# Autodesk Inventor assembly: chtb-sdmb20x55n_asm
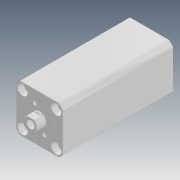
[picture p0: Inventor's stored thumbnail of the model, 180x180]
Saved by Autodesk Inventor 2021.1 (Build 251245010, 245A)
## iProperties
Company: Microsoft
Created: 2018-05
Part Number: chtb-sdmb20x55n_asm
Description: STEP AP214
Document SubType Name: Assembly
Designer: user
Title: chtb-sdmb20x55n_asm.STEP
Author: Windows
Revision Number: ÈÎºÎ
Sending System: SolidWorks 2015
Preprocessor: SwSTEP 2.0
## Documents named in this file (4)
- D:\Vault_2016\Projekty\Clamptek\Hydraulic\CHTB\CHTB-20\Inventor\CHTB-SDMB20x55N\chtb-sdmb20x55n_asm.iam
- D:\Vault_2016\Projekty\Clamptek\Hydraulic\CHTB\CHTB-20\Inventor\CHTB-SDMB20x55N\CHTB-SDMB20X55NBT.ipt
- D:\Vault_2016\Projekty\Clamptek\Hydraulic\CHTB\CHTB-20\Inventor\CHTB-SDMB20x55N\CHTB-SDMB20X55NHSG.ipt
- D:\Vault_2016\Projekty\Clamptek\Hydraulic\CHTB\CHTB-20\Inventor\CHTB-SDMB20x55N\QG_3.ipt
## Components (3 placed, 3 different names)
1. CHTB-SDMB20X55NBT_1
2. CHTB-SDMB20X55NHSG_2
3. QG_3_3
